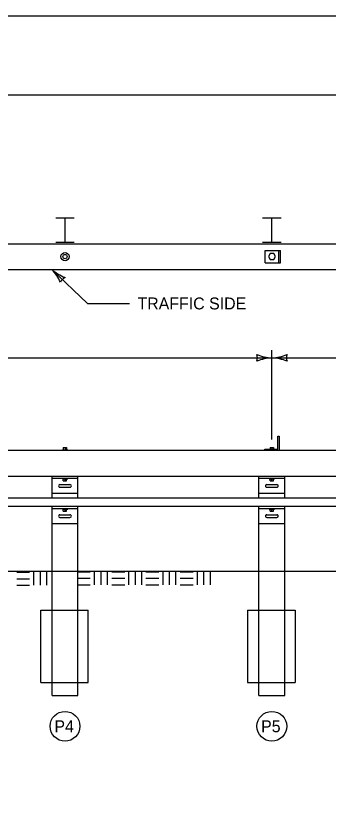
# Model space of a CAD drawing. Extents: x 49991.4 to 50021, y 49987.6 to 50011.4.
# Drawn here: x 50004.991 to 50006.567, y 49995.029 to 49998.999 of the extents above; entities that cross this region are included whole.
import ezdxf

# ---------------------------------------------------------------- set-up
doc = ezdxf.new("R2010")
doc.units = 0
for name, color, linetype in [('Level 1', 7, 'Continuous'), ('Level 2', 7, 'Continuous'), ('Level 3', 7, 'Continuous'), ('Level 4', 7, 'Continuous')]:
    doc.layers.add(name, color=color, linetype=linetype)

msp = doc.modelspace()

# ---------------------------------------------------------------- linework, layer by layer
at = {"layer": 'Level 1'}
for p, q in [((50005.1927, 49997.982), (50005.2859, 49997.982)), ((50005.2397, 49997.8587), (50005.2397, 49997.982)), ((50006.236, 49997.982), (50006.3293, 49997.982)), ((50006.2831, 49997.8587), (50006.2831, 49997.982)), ((50001.743, 49997.8514), (50015.4519, 49997.8514)), ((50005.1927, 49997.8587), (50005.2859, 49997.8587)), ((50006.236, 49997.8587), (50006.3293, 49997.8587)), ((50006.2485, 49997.818), (50006.3255, 49997.818)), ((50006.2486, 49997.7548), (50006.2486, 49997.818)), ((50006.3171, 49997.7548), (50006.3171, 49997.818)), ((50006.3257, 49997.7548), (50006.3257, 49997.818)), ((50006.2485, 49997.7548), (50006.3255, 49997.7548)), ((50001.743, 49997.7218), (50015.4519, 49997.7218)), ((50006.3133, 49996.8177), (50006.3133, 49996.8831)), ((50006.3133, 49996.8831), (50006.3192, 49996.8831)), ((50006.3192, 49996.8831), (50006.3192, 49996.8116)), ((50002.0298, 49996.8116), (50015.4519, 49996.8116)), ((50005.1749, 49996.8116), (50005.3045, 49996.8116)), ((50005.2264, 49996.8144), (50005.2539, 49996.8144)), ((50005.2264, 49996.8116), (50005.2264, 49996.8144)), ((50005.2308, 49996.825), (50005.2477, 49996.825)), ((50005.2308, 49996.825), (50005.2308, 49996.8144)), ((50005.2397, 49996.825), (50005.2397, 49996.8144)), ((50005.2477, 49996.825), (50005.2477, 49996.8144)), ((50005.2539, 49996.8116), (50005.2539, 49996.8144)), ((50006.2174, 49996.8116), (50006.3478, 49996.8116)), ((50006.2478, 49996.8118), (50006.2478, 49996.8177)), ((50006.2478, 49996.8177), (50006.3133, 49996.8177)), ((50006.2688, 49996.8144), (50006.2963, 49996.8144)), ((50006.2688, 49996.8116), (50006.2688, 49996.8144)), ((50006.2742, 49996.825), (50006.2911, 49996.825)), ((50006.2742, 49996.825), (50006.2742, 49996.8144)), ((50006.2831, 49996.825), (50006.2831, 49996.8144)), ((50006.2911, 49996.825), (50006.2911, 49996.8144)), ((50006.2963, 49996.8116), (50006.2963, 49996.8144)), ((50002.0298, 49996.6812), (50015.4519, 49996.6812)), ((50005.1749, 49996.5719), (50005.1749, 49996.6812)), ((50005.1749, 49996.6705), (50005.3045, 49996.6705)), ((50005.2264, 49996.6705), (50005.2264, 49996.6679)), ((50005.2264, 49996.6679), (50005.2539, 49996.6679)), ((50005.2308, 49996.6572), (50005.2308, 49996.6679)), ((50005.2397, 49996.6572), (50005.2397, 49996.6679)), ((50005.2477, 49996.6572), (50005.2477, 49996.6679)), ((50005.2539, 49996.6705), (50005.2539, 49996.6679)), ((50005.3045, 49996.5719), (50005.3045, 49996.6812)), ((50006.2174, 49996.5719), (50006.2174, 49996.6812)), ((50006.2174, 49996.6705), (50006.3478, 49996.6705)), ((50006.2688, 49996.6705), (50006.2688, 49996.6679)), ((50006.2688, 49996.6679), (50006.2963, 49996.6679)), ((50006.2742, 49996.6572), (50006.2742, 49996.6679)), ((50006.2831, 49996.6572), (50006.2831, 49996.6679)), ((50006.2911, 49996.6572), (50006.2911, 49996.6679)), ((50006.2963, 49996.6705), (50006.2963, 49996.6679)), ((50006.3478, 49996.5719), (50006.3478, 49996.6812)), ((50005.2131, 49996.6389), (50005.2646, 49996.6389)), ((50005.2308, 49996.6572), (50005.2477, 49996.6572)), ((50006.2571, 49996.6389), (50006.3095, 49996.6389)), ((50006.2742, 49996.6572), (50006.2911, 49996.6572)), ((50005.1749, 49996.595), (50005.3045, 49996.595)), ((50005.214, 49996.6253), (50005.2646, 49996.6253)), ((50006.2174, 49996.595), (50006.3478, 49996.595)), ((50006.2571, 49996.6253), (50006.3077, 49996.6253)), ((50002.0449, 49996.5719), (50012.5032, 49996.5719)), ((50002.0449, 49996.5294), (50007.0485, 49996.5294)), ((50005.1749, 49996.2026), (50005.1749, 49996.5294)), ((50005.1749, 49996.5187), (50005.3045, 49996.5187)), ((50005.2264, 49996.5187), (50005.2264, 49996.5152)), ((50005.2264, 49996.5152), (50005.2539, 49996.5152)), ((50005.2308, 49996.5044), (50005.2308, 49996.5152)), ((50005.2397, 49996.5044), (50005.2397, 49996.5152)), ((50005.2477, 49996.5044), (50005.2477, 49996.5152)), ((50005.2539, 49996.5187), (50005.2539, 49996.5152)), ((50005.3045, 49996.2026), (50005.3045, 49996.5294)), ((50006.2174, 49996.2026), (50006.2174, 49996.5294)), ((50006.2174, 49996.5187), (50006.3478, 49996.5187)), ((50006.2688, 49996.5187), (50006.2688, 49996.5152)), ((50006.2688, 49996.5152), (50006.2963, 49996.5152)), ((50006.2742, 49996.5044), (50006.2742, 49996.5152)), ((50006.2831, 49996.5044), (50006.2831, 49996.5152)), ((50006.2911, 49996.5044), (50006.2911, 49996.5152)), ((50006.2963, 49996.5187), (50006.2963, 49996.5152)), ((50006.3478, 49996.2026), (50006.3478, 49996.5294)), ((50005.2131, 49996.4868), (50005.2646, 49996.4868)), ((50005.214, 49996.4732), (50005.2646, 49996.4732)), ((50005.2308, 49996.5044), (50005.2477, 49996.5044)), ((50006.2561, 49996.4868), (50006.3085, 49996.4868)), ((50006.2571, 49996.4732), (50006.3077, 49996.4732)), ((50006.2742, 49996.5044), (50006.2911, 49996.5044)), ((50005.1749, 49996.4422), (50005.3045, 49996.4422)), ((50006.2174, 49996.4422), (50006.3478, 49996.4422)), ((50001.5626, 49996.2026), (50015.4519, 49996.2026)), ((50004.9964, 49996.1974), (50005.0614, 49996.1974)), ((50005.0831, 49996.1324), (50005.0831, 49996.1974)), ((50005.1156, 49996.1324), (50005.1156, 49996.1974)), ((50005.1481, 49996.1324), (50005.1481, 49996.1974)), ((50005.3021, 49996.1992), (50005.3671, 49996.1992)), ((50005.3888, 49996.1342), (50005.3888, 49996.1992)), ((50005.4213, 49996.1342), (50005.4213, 49996.1992)), ((50005.4538, 49996.1342), (50005.4538, 49996.1992)), ((50005.4754, 49996.1992), (50005.5405, 49996.1992)), ((50005.5622, 49996.1342), (50005.5622, 49996.1992)), ((50005.5946, 49996.1342), (50005.5946, 49996.1992)), ((50005.6271, 49996.1342), (50005.6271, 49996.1992)), ((50005.6474, 49996.1992), (50005.7124, 49996.1992)), ((50005.7341, 49996.1342), (50005.7341, 49996.1992)), ((50005.7666, 49996.1342), (50005.7666, 49996.1992)), ((50005.7991, 49996.1342), (50005.7991, 49996.1992)), ((50005.8207, 49996.1992), (50005.8858, 49996.1992)), ((50005.9075, 49996.1342), (50005.9075, 49996.1992)), ((50005.9399, 49996.1342), (50005.9399, 49996.1992)), ((50005.9724, 49996.1342), (50005.9724, 49996.1992)), ((50004.9964, 49996.1649), (50005.0614, 49996.1649)), ((50005.3021, 49996.1667), (50005.3671, 49996.1667)), ((50005.4754, 49996.1667), (50005.5405, 49996.1667)), ((50005.6474, 49996.1667), (50005.7124, 49996.1667)), ((50005.8207, 49996.1667), (50005.8858, 49996.1667)), ((50004.9964, 49996.1324), (50005.0614, 49996.1324)), ((50005.3021, 49996.1342), (50005.3671, 49996.1342)), ((50005.4754, 49996.1342), (50005.5405, 49996.1342)), ((50005.6474, 49996.1342), (50005.7124, 49996.1342)), ((50005.8207, 49996.1342), (50005.8858, 49996.1342))]:
    msp.add_line(p, q, dxfattribs=at)
for points in [[(49999.3835, 49998.9992), (50016.7501, 49998.9992), (50016.7501, 49987.7988), (49999.3835, 49987.7988)], [(50006.2737, 49997.7716), (50006.2926, 49997.7716), (50006.3008, 49997.7866), (50006.2926, 49997.8016), (50006.2737, 49997.8016), (50006.2655, 49997.7866)]]:
    msp.add_lwpolyline(points, close=True, dxfattribs=at)
for radius in [0.0209, 0.0109]:
    msp.add_circle((50005.2397, 49997.7866), radius, dxfattribs=at)
for centre, start, end in [((50005.2136, 49996.6321), 86.0196, 273.9804), ((50005.2651, 49996.6321), 266.0196, 93.9804), ((50006.2566, 49996.6321), 86.0196, 273.9804), ((50006.3082, 49996.6321), 266.0196, 93.9804), ((50005.2136, 49996.48), 86.0196, 273.9804), ((50005.2651, 49996.48), 266.0196, 93.9804), ((50006.2566, 49996.48), 86.0196, 273.9804), ((50006.3082, 49996.48), 266.0196, 93.9804)]:
    msp.add_arc(centre, 0.00681, start, end, dxfattribs=at)
at = {"layer": 'Level 2'}
for centre in [(50005.2397, 49995.4216), (50006.2826, 49995.4216)]:
    msp.add_circle(centre, 0.075, dxfattribs=at)
at = {"layer": 'Level 3'}
for p, q in [((50001.5626, 49998.6017), (50014.9504, 49998.6017)), ((50005.1733, 49997.7218), (50005.3533, 49997.5507)), ((50005.3533, 49997.5507), (50005.5651, 49997.5507)), ((50006.2831, 49996.865), (50006.2831, 49997.3163)), ((50002.1107, 49997.2763), (50006.2831, 49997.2763)), ((50006.2831, 49997.2763), (50007.8468, 49997.2763))]:
    msp.add_line(p, q, dxfattribs=at)
for centre, radius, start, end in [((50005.0136, 49997.5671), 0.2223, 23.9084, 44.0919), ((50005.3253, 49997.8984), 0.233, 229.2797, 248.5295), ((50005.2662, 49997.6335), 0.0548, 118.5912, 154.3135), ((50006.2923, 49997.4984), 0.2223, 247.456, 267.6395), ((50006.1549, 49997.2763), 0.0548, 342.1388, 17.8612), ((50006.2946, 49997.0436), 0.233, 92.8273, 112.0772), ((50006.2716, 49997.509), 0.233, 272.8273, 292.0772), ((50006.2739, 49997.0542), 0.2223, 67.456, 87.6395), ((50006.4113, 49997.2763), 0.0548, 162.1388, 197.8612)]:
    msp.add_arc(centre, radius, start, end, dxfattribs=at)
at = {"layer": 'Level 4'}
for p, q in [((50005.1749, 49995.5766), (50005.1749, 49996.2026)), ((50005.3045, 49995.5766), (50005.3045, 49996.2026)), ((50006.2174, 49995.5766), (50006.2174, 49996.2026)), ((50006.3478, 49995.5766), (50006.3478, 49996.2026)), ((50005.1182, 49996.0072), (50005.356, 49996.0072)), ((50005.1182, 49995.6414), (50005.1182, 49996.0072)), ((50005.356, 49995.6414), (50005.356, 49996.0072)), ((50006.1597, 49996.0072), (50006.3994, 49996.0072)), ((50006.1597, 49996.0072), (50006.1597, 49995.6414)), ((50006.3994, 49996.0072), (50006.3994, 49995.6414)), ((50005.1182, 49995.6414), (50005.356, 49995.6414)), ((50006.1597, 49995.6414), (50006.3994, 49995.6414)), ((50005.1749, 49995.5766), (50005.3045, 49995.5766)), ((50006.2174, 49995.5766), (50006.3478, 49995.5766))]:
    msp.add_line(p, q, dxfattribs=at)

# ---------------------------------------------------------------- texts
at = {"layer": 'Level 2'}
for s, p in [('TRAFFIC SIDE', (50005.6051, 49997.5207)), ('P4', (50005.1864, 49995.3917)), ('P5', (50006.2284, 49995.3917))]:
    msp.add_text(s, height=0.06, dxfattribs=at).set_placement(p)

doc.saveas('drawing.dxf')
